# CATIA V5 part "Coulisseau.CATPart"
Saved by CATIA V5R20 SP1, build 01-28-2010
Part number: Coulisseau
Bounding box of the stored display mesh (mm): x -40 to 20, y -20 to 20, z -10 to 10
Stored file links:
  C:\Documents and Settings\ndumont\Bureau\ndumont_CAO\Coulisseau.CATPart
  C:\Documents and Settings\ndumont\Bureau\ndumont_CAO\ndumont.CATProduct
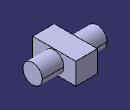
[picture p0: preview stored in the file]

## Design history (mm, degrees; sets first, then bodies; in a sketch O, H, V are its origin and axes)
External parameters (linked from other documents)
  External.DiametreTrousABetDC = 18 mm
  External.EpaisseurCoulisseau = 20 mm
  External.EpaisseurABetDC = 20 mm
Set1
  Line1 to Line4: linked copy from another document
  Point1: linked copy from another document
Body1 (main body)
  Sketch1 on yz-plane, origin (0, 0, 0), H (0, 1, 0), V (0, 0, 1)
    line L1 (-20, 10) -> (20, 10)
    line L2 (20, 10) -> (20, -10)
    line L3 (20, -10) -> (-20, -10)
    line L4 (-20, -10) -> (-20, 10)
    reference projected line E1 (98.3215, 10) -> (138.3215, 10) from Line1
    reference projected line E2 (20, 10) -> (20, -10) from Line2
    reference projected line E3 (138.3215, -10) -> (98.3215, -10) from Line3
    reference projected line E4 (-20, -10) -> (-20, 10) from Line4
    horizontal: L1 H, L3 H
    vertical: L2 V, L4 V
    coincidence: L1 E1, L2 E2, E3 L3, E4 L4
  Pad1: profile Sketch1, direction (-1, 0, 0), length 20 {= External.EpaisseurCoulisseau}
  Sketch2 on start face of Pad1, origin (0, 0, 0), H (0, 1, 0), V (0, 0, 1)
    circle A1 centre (0, 0) radius 9
    point P1 (0, 0)
    reference projected point E1 (0, 0) from Point1
    radius A1 = 9 {= External.DiametreTrousABetDC /2}
    coincidence: P1 E1
  Pad2: profile Sketch2, direction (1, 0, 0), length 20 {= External.EpaisseurABetDC}
  Sketch3 on end face of Pad1, origin (-20, 0, 0), H (0, -1, 0), V (0, 0, 1)
    circle A1 centre (0, 0) radius 9
    point P1 (0, 0)
    reference projected point E1 (0, 0) from Point1
    radius A1 = 9 {= External.DiametreTrousABetDC /2}
    coincidence: E1 P1
  Pad3: profile Sketch3, direction (-1, 0, 0), length 20 {= External.EpaisseurABetDC}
